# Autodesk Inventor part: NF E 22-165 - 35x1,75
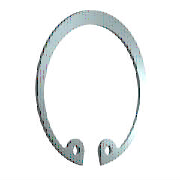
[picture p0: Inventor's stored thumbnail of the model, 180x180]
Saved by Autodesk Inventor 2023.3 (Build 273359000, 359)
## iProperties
IsCustomPart: 0
Created: 2022-02
Part Number: NF E 22-165 - 35x1,75
Material: Acier, doux
Description: Rondelle élastique d´arrêt
Document SubType Name: Modeling
Standard: NF E 22-165
Designer: Thier
Standards Organization: AFNOR
Language: fr-FR
Size Designation: 35x1,75
Categories: <MemberInstance><Categories><Category DisplayName="Pièces d'arbre" InternalName="7f7aeb1f-a693-4053-b835-cee3144e0d98" Mnemonic="SHFT"><Category DisplayName="An
Density: 7.85 g/cm^3
Appearance: Semi-poli
Author: Thier
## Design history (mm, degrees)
sketch "Esquisse1"
  geometry: L1 (0, 15.113)-(0, -73.177) reference; L2 (-45.5, 0)-(45.5, 0) reference; L3 (-4.964, 1.5)-(1.502, 1.5); L4 (0, -2.3)-(-5.307, -2.3); L5 (0, -17)-(-8.583, -33.388); L6 (-8.583, -33.388)-(-21.772, -26.481); L7 (-7.191, -30.731)-(-17.446, -25.36); L8 (-4.977, -31.891)-(-6.29, -34.398); L9 (4.977, -31.891)-(6.29, -34.398); C1 r 1.25 at (-7.191, -30.731); C2 r 1.25 at (7.191, -30.731); A1 r 15.65 centre (0, -17.95) between (11.833, -28.192) and (-11.833, -28.192); A2 r 18.5 centre (0, -17) between (6.29, -34.398) and (-6.29, -34.398); A3 r 2.5 centre (-7.191, -30.731) between (-4.977, -31.891) and (-8.567, -28.643); A4 r 2.5 centre (-9.943, -26.556) between (-11.833, -28.192) and (-8.567, -28.643); A5 r 2.5 centre (9.943, -26.556) between (8.567, -28.643) and (11.833, -28.192); A6 r 2.5 centre (7.191, -30.731) between (8.567, -28.643) and (4.977, -31.891); 3 further points
  constraints: 15 point on circle, 14 end point, 9 symmetric about line, 8 centre point, 6 tangent, 4 coincident, 4 point on line, 3 perpendicular, 1 parallel, 4 other
  dimensions: "d8" = 0.95 distance of A1.centre L5.start (= 0.25 x SRB1); "d38" = 3.8 distance between parallel lines of L4 L3 (= SRB1); "d39" = 17 distance from line of L5.start L2 (= 0.5 x WD); "d43" = 18.5 radius of A2 (= 0.5 x ND); "d45" = 3 distance between parallel lines of L7 L6 (= 0.5 x SRB2); "d46" = 2.5 radius of A4 (= SD5); "d47" = 6.29 distance from line of L1 L8.end (= 0.17 x ND); "d48" = 2.5 diameter of C1 (= SD5); "d49" = 2.5 radius of A3 (= SD5)
extrude "Corps" new body sketch "Esquisse1" distance "d2" = 1.75 (= SD); taper "d3" = 0 deg
workaxis "Work Axis1"
workaxis "Work Axis2"
workplane "Work Plane1"
body "Solid1"
other parameters: "WD" = 34 (= WDMIN) [user parameter; used in 1 equation term], "SD" = 1.75 [user parameter; used in 1 equation term], "SRB1" = 3.8 [user parameter; used in 2 equation terms], "ND" = 37 [user parameter; used in 2 equation terms], "SRB2" = 6 [user parameter; used in 1 equation term], "SD5" = 2.5 [user parameter; used in 3 equation terms], "d50" = 0, "d51" = 0, "d52" = 0, "d53" = 0, "WDMIN" = 34 [user parameter; used in 1 equation term], "SD6" = 37.8 [user parameter], "NND" = 35 [user parameter; used in 1 equation term], "WDMAX" = 35 (= NND) [user parameter]
